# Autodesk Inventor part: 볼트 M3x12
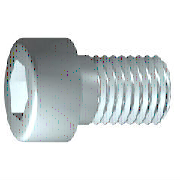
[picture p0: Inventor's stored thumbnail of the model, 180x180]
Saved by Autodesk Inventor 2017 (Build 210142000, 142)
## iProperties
IsCustomPart: 0
Created: 2012-02
Part Number: 볼트 M3x12
Material: 강철, 연강
Description: 6각머리 태핑 나사
Document SubType Name: Modeling
Standard: KS B 1003
Designer: mduedu
Standards Organization: KS
Language: ko-KR
Size Designation: M 3 x 12
Categories: <MemberInstance><Categories><Category DisplayName="조임쇠" InternalName="e4da775c-781d-43d5-af7c-5136215cf5a6" Mnemonic="FSTN"><Category DisplayName="볼트" InternalN
Density: 7.86 g/cm^3
Mass: 1.15208 g
Surface Area: 2.207 cm^2
Volume: 0.146575 cm^3
Appearance: 강철
Author: mduedu
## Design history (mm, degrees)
sketch "스케치1"
  geometry: L1 (-0.867, 0)-(12, 0); L2 (12, 0)-(12, 1.5); L3 (12, 1.5)-(1.25, 1.5); L4 (1.25, 1.5)-(0.943, 1.5); L5 (0.943, 1.5)-(0, 1.5); L6 (0, 1.5)-(0, 2.75); L7 (0, 2.75)-(-3, 2.75); L8 (-3, 2.75)-(-3, 1.443); L9 (-3, 1.443)-(-1.7, 1.443); L10 (-1.7, 1.443)-(-0.867, 0); L11 (-6, 0)-(15, 0) reference; L12 (0, -0.55)-(0, 3.3) reference; L13 (1.25, 1.5)-(0, 1.5)
  constraints: 22 end point, 6 parallel, 2 collinear, 2 perpendicular, 1 horizontal, 1 point on line
  dimensions: "d1" = 10.75 distance from line of L3.end L2 (= GEL); "d2" = 0.30683 distance of L4.end L3.end (computed from GAL); "d3" = 3 distance between parallel lines of L8 L6 (= KOH); "d4" = 1.3 distance of L8.end L9.end (= INTI); "d5" = 60 deg angle of L10 L1; "d6" = 3 diameter of L3 L1 (= GD); "d7" = 3 diameter of L5 L1 (= BDM); "d8" = 2.88675 diameter of L9 L1 (= 1.1547 x SW); "d9" = 5.5 diameter of L7 L1 (= KOD); "d26" = 12 distance between parallel lines of L12 L2 (= NLG)
revolve "본체" sketch "스케치1" stored, may be unused: angle "d10" = 90 deg
sketch "스케치2"
  geometry: L1 (0, -3.85)-(0, 3.85) reference; L2 (-3.85, 0)-(3.85, 0) reference; L3 (1.443, 0)-(0.722, -1.25); L4 (0.722, -1.25)-(-0.722, -1.25); L5 (-0.722, -1.25)-(-1.443, 0); L6 (-1.443, 0)-(-0.722, 1.25); L7 (-0.722, 1.25)-(0.722, 1.25); L8 (0.722, 1.25)-(1.443, 0); 2 further points
  constraints: 12 end point, 1 coincident, 1 horizontal alignment, 1 point on line, 12 other
extrude "슬롯" join sketch "스케치2" stored distance "d11" = 10; taper "d12" = 0 deg
workplane "Work Plane1"
fillet "Fillet2" dims "d30" = 0.1 (= R)
body "Solid1"
fillet "모깎기1" dims "d17" = 0.3 (= RR)
feature "스레드" dims "d13" = 10.75 (= GEL), "d14" = 0
chamfer "모따기1" distance "d15" = 0.30673 (= -0.5 x SPD + 0.5 x GD); stored, may be unused: second distance "d16" = 0.30673 (= GUL), angle "d27" = 45 deg
other parameters: "GD" = 3 (= NND) [user parameter; used in 2 equation terms], "NLG" = 12 [user parameter; used in 1 equation term], "GEL" = 10.75 [user parameter; used in 2 equation terms], "KOD" = 5.5 [user parameter; used in 1 equation term], "KOH" = 3 [user parameter; used in 1 equation term], "INTI" = 1.3 [user parameter; used in 1 equation term], "GAL" = 0.30673 (= 0.61345 x PTC) [user parameter; used in 1 equation term], "GUL" = 0.30673 (= 0.61345 x PTC) [user parameter; used in 1 equation term], "BDM" = 3 (= NND) [user parameter; used in 1 equation term], "SW" = 2.5 [user parameter; used in 2 equation terms], "RR" = 0.3 [user parameter; used in 1 equation term], "SPD" = 2.38655 (= NND - 1.2269 x PTC) [user parameter; used in 1 equation term], "d19" = 0, "d28" = 0, "d29" = 0, "R" = 0.1 [user parameter; used in 1 equation term], "PHH" = 0.1 [user parameter], "GD1" = 2.38655 (= THREADDIA - 1.2269 x PTC) [user parameter], "THREADDIA" = 3 [user parameter; used in 1 equation term], "FAWI" = 45 deg [user parameter], "PTC" = 0.5 [user parameter; used in 5 equation terms], "NND" = 3 [user parameter; used in 3 equation terms], "TOA" = 30 deg [user parameter], "E0" = 2.8875 (= 1.155 x SW) [user parameter]
